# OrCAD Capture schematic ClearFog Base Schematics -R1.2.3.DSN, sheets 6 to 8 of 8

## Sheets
6 MicroUSB_UART + Fan + SFP: size C; title: MikroUSB_UART + Fan + SFP
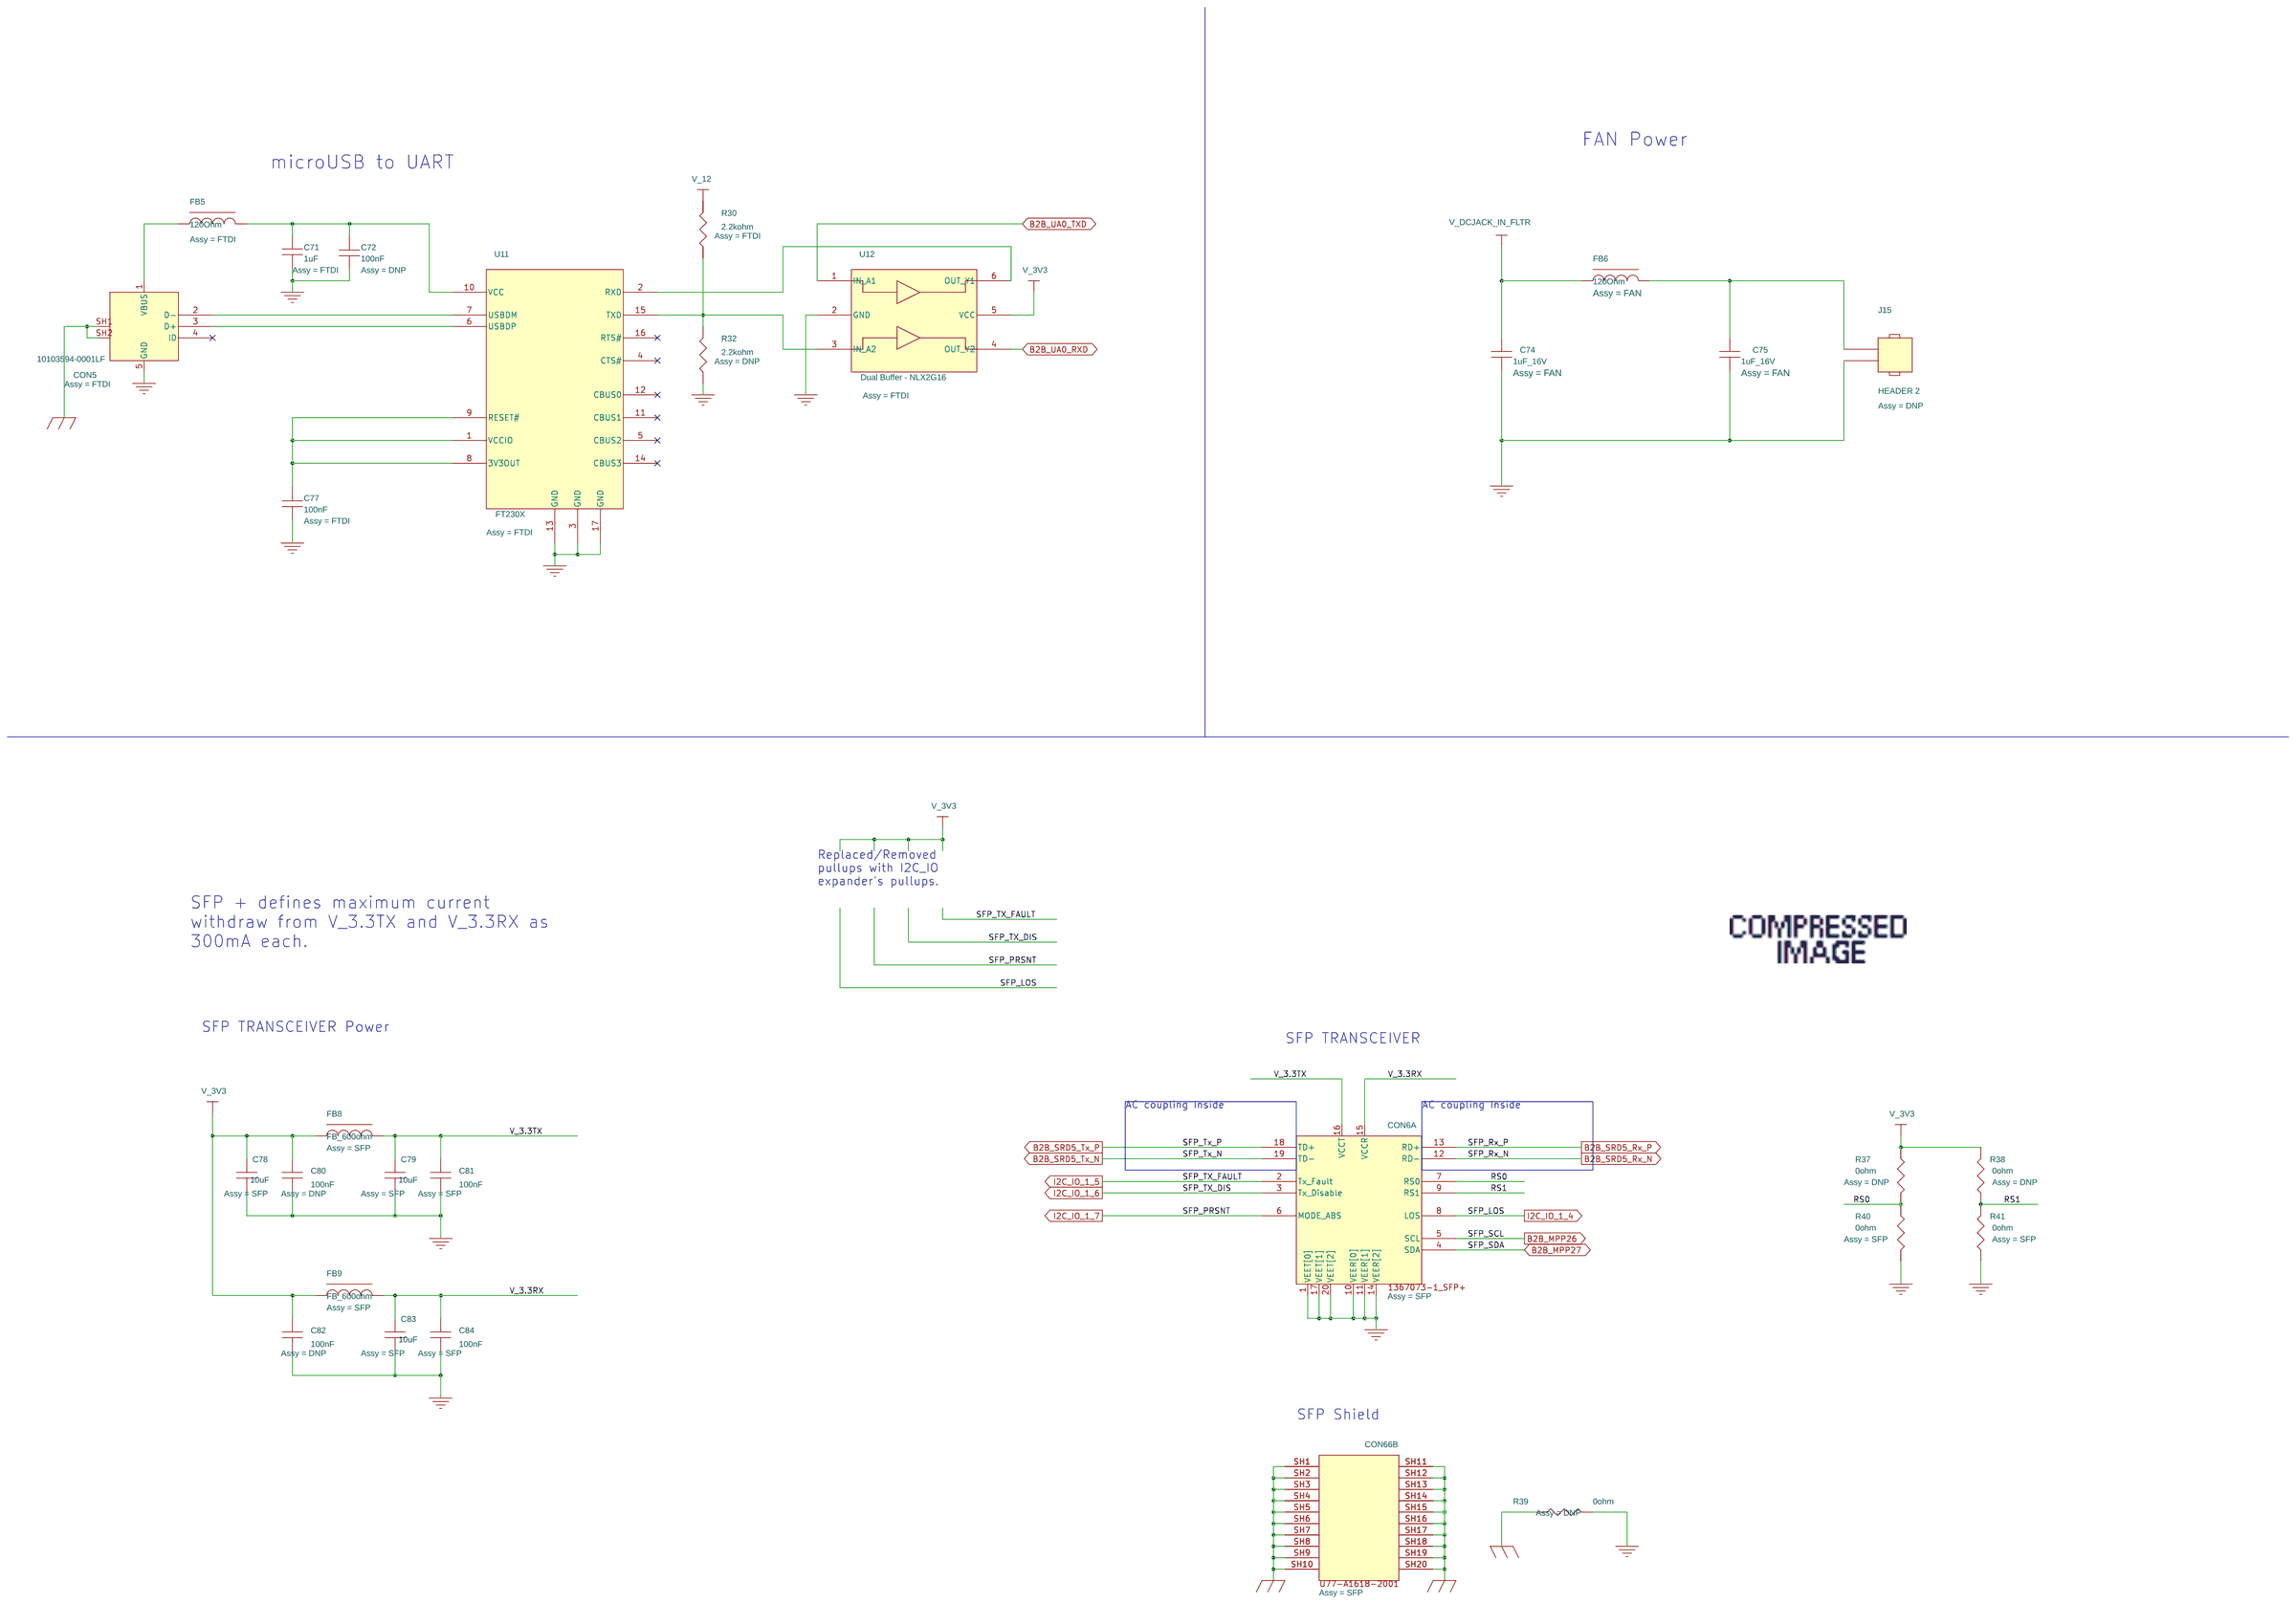
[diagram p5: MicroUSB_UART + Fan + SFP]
7 GE PHY1 + RJ45: size C; title: GE PHY1 + RJ45
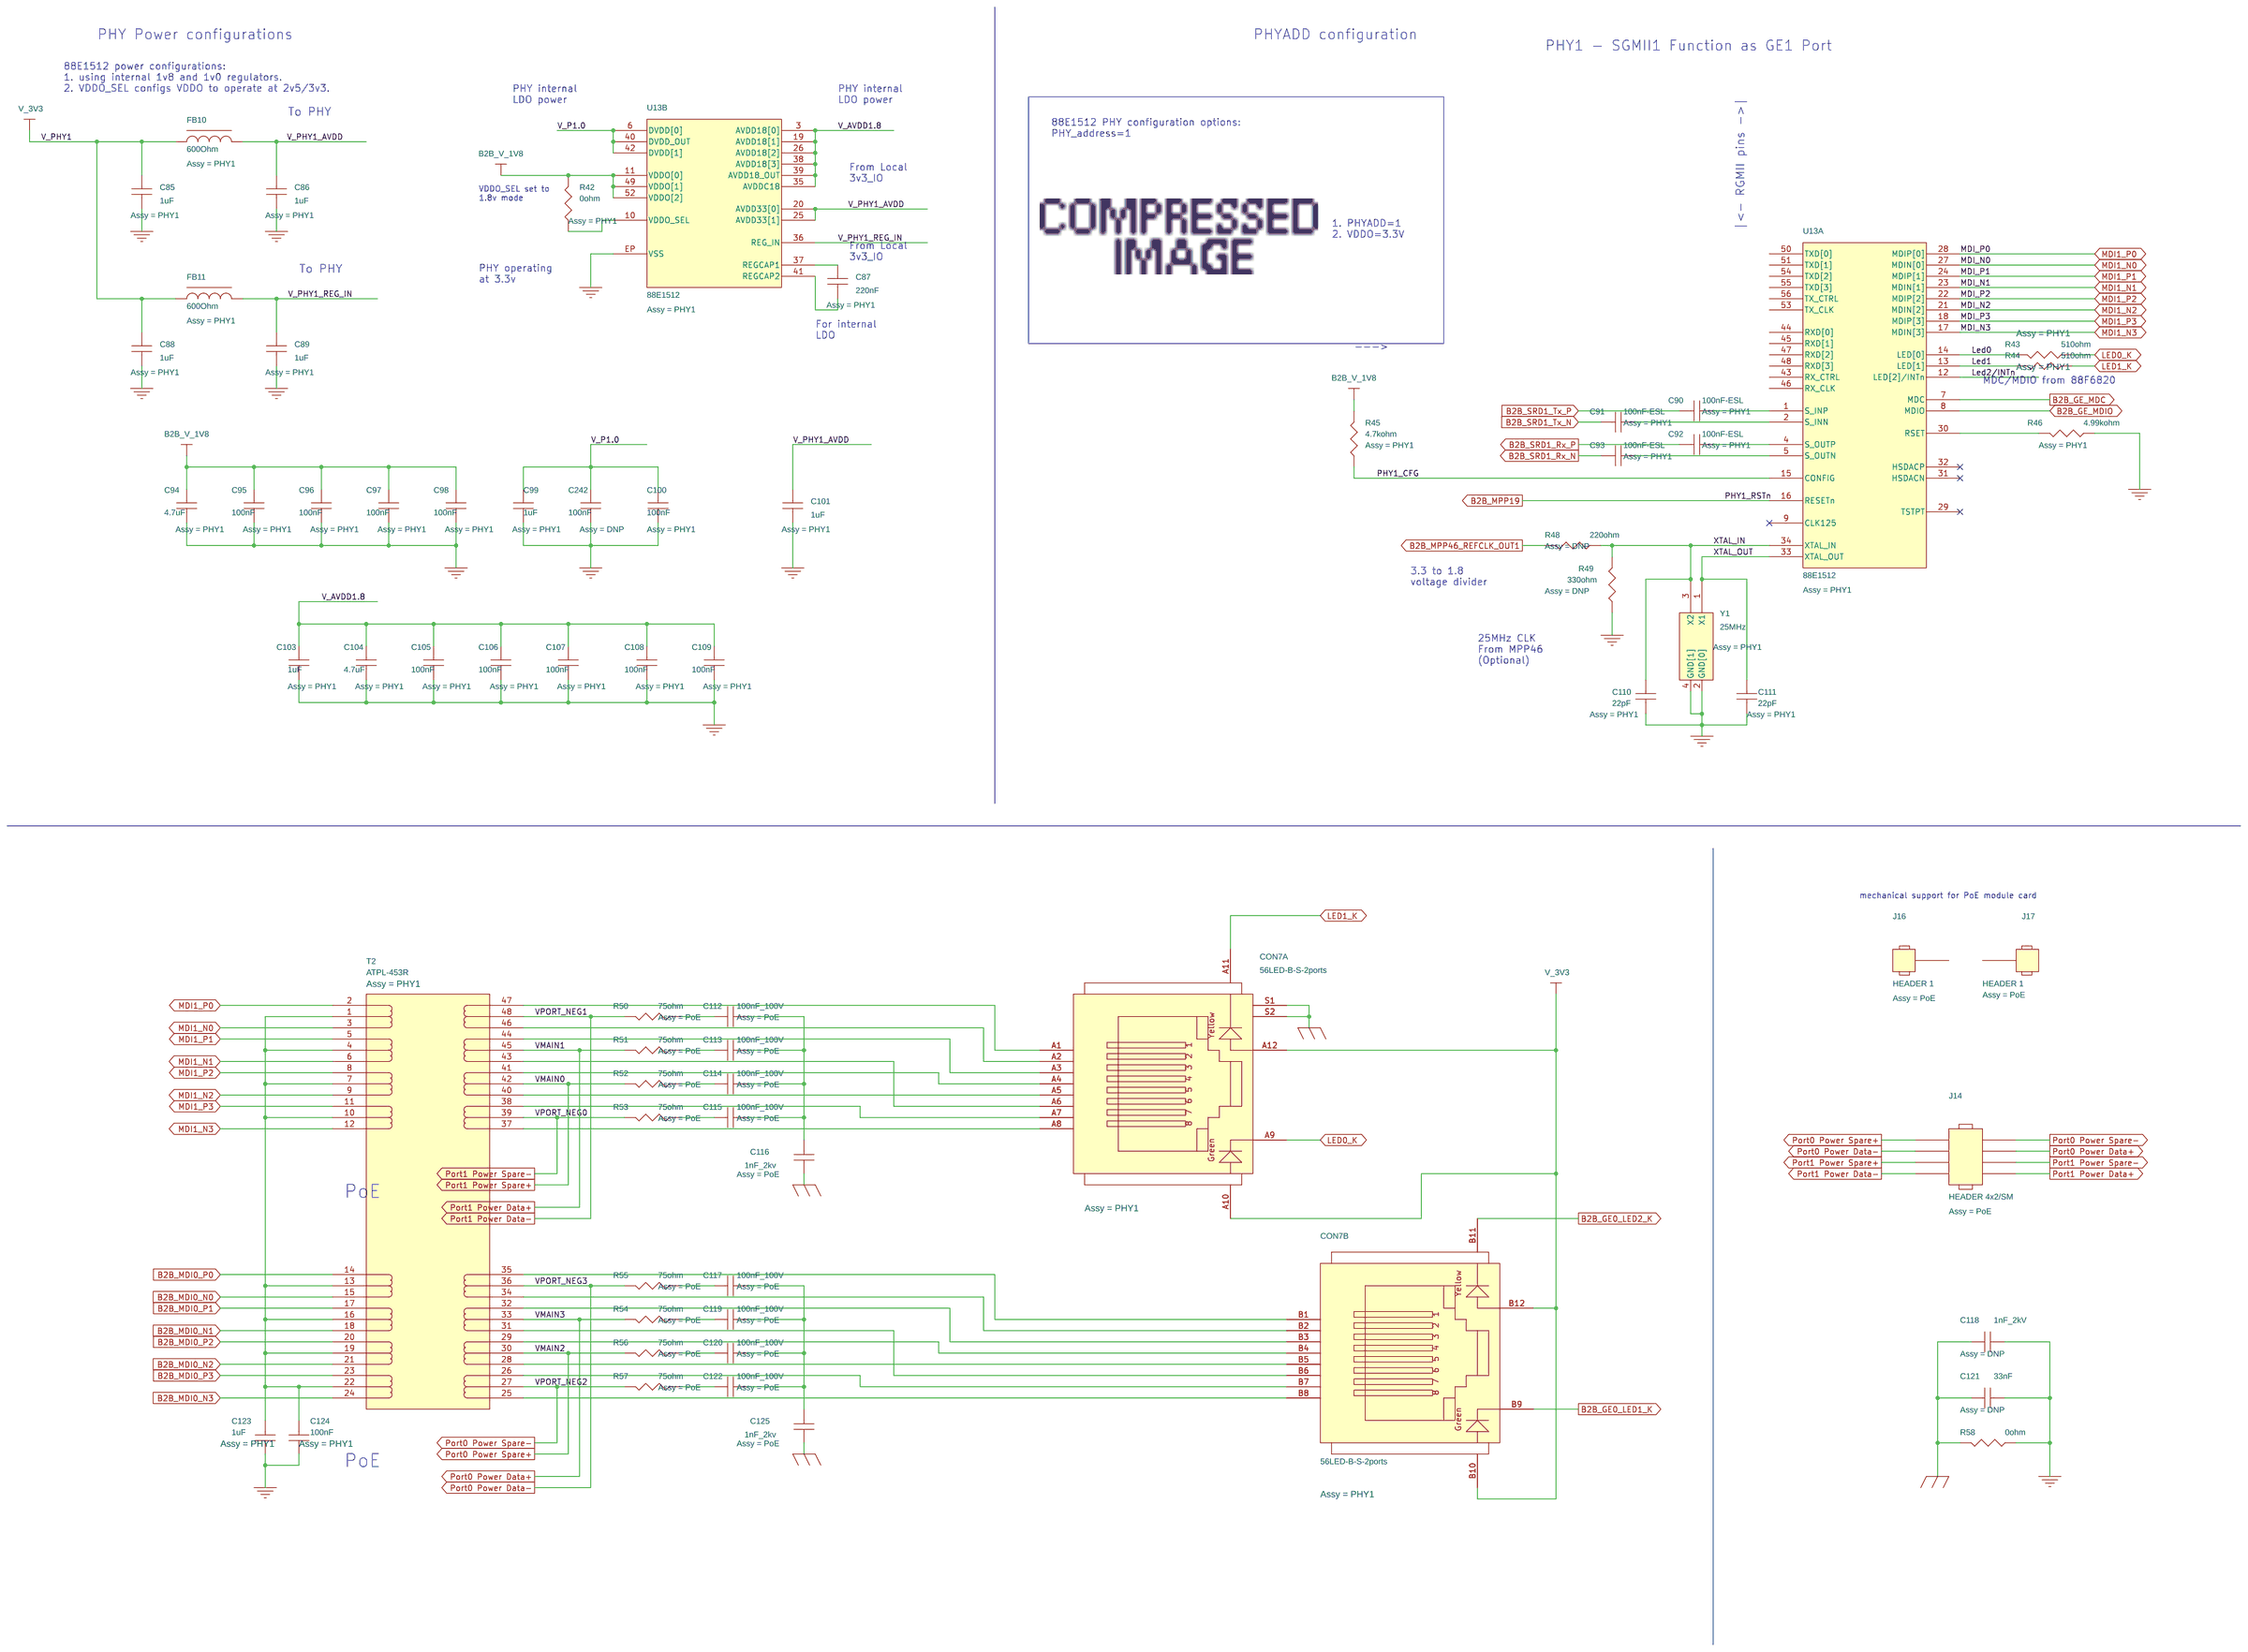
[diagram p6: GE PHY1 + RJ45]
8 Mikrobus + Booting + IO_Ex: size C; title: Mikrobus + Booting + IO_Ex
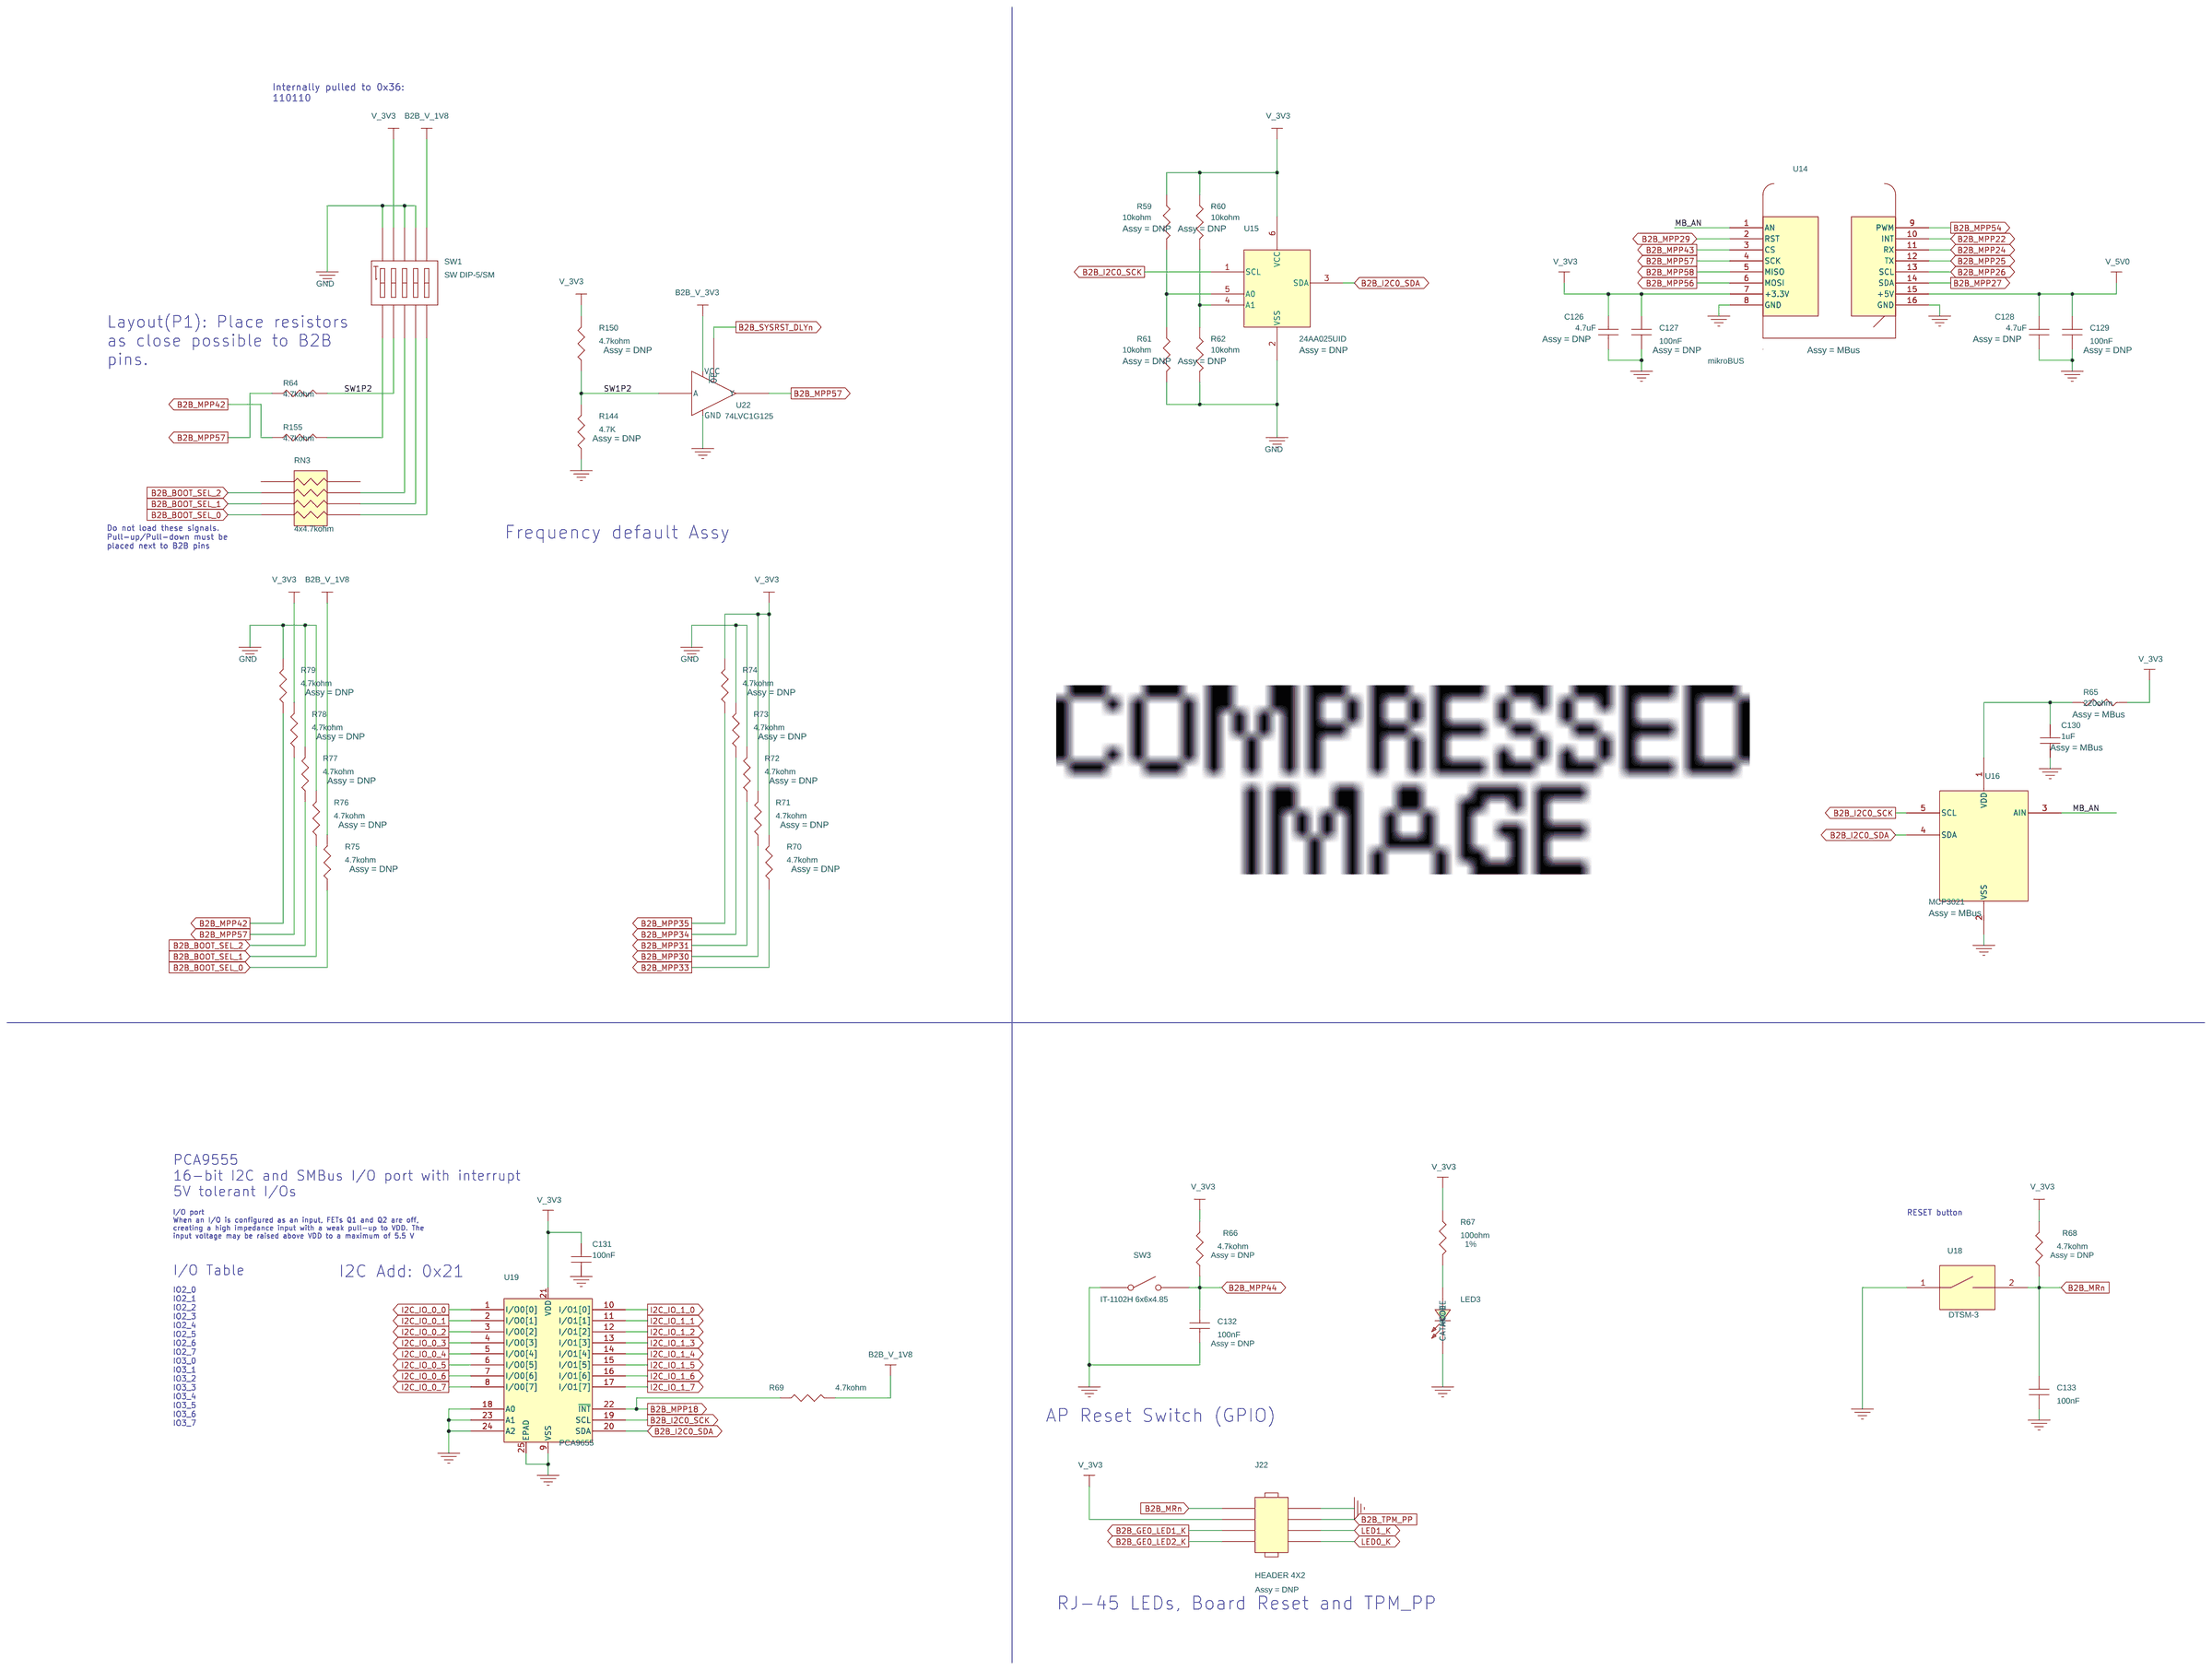
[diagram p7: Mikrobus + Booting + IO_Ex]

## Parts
sheet GE PHY1 + RJ45
C85  1uF  [C0402]
C86  1uF  [C0402]
C87  220nF  [C0402]
C88  1uF  [C0402]
C89  1uF  [C0402]
C90  100nF-ESL  [C0402]
C91  100nF-ESL  [C0402]
C92  100nF-ESL  [C0402]
C93  100nF-ESL  [C0402]
C94  4.7uF  [C0603]
C95  100nF  [C0402]
C96  100nF  [C0402]
C97  100nF  [C0402]
C98  100nF  [C0402]
C99  1uF  [C0402]
C100  100nF  [C0402]
C101  1uF  [C0402]
C103  1uF  [C0402]
C104  4.7uF  [C0603]
C105  100nF  [C0402]
C106  100nF  [C0402]
C107  100nF  [C0402]
C108  100nF  [C0402]
C109  100nF  [C0402]
C110  22pF  [C0402]
C111  22pF  [C0402]
C112  100nF_100V  [C0603]
C113  100nF_100V  [C0603]
C114  100nF_100V  [C0603]
C115  100nF_100V  [C0603]
C116  1nF_2kv  [C1210]
C117  100nF_100V  [C0603]
C118  1nF_2kV  [C1210]
C119  100nF_100V  [C0603]
C120  100nF_100V  [C0603]
C121  33nF  [C0402]
C122  100nF_100V  [C0603]
C123  1uF  [C0402]
C124  100nF  [C0402]
C125  1nF_2kv  [C1210]
C242  100nF  [C0402]
CON7  56LED-B-S-2ports  [RJ45x2]  (sections A,B)
FB10  600Ohm  [L0603]
FB11  600Ohm  [L0603]
J14  HEADER 4x2/SM
J16  HEADER 1
J17  HEADER 1
R42  0ohm  [R0402]
R43  510ohm  [R0402]
R44  510ohm  [R0402]
R45  4.7kohm  [R0402]
R46  4.99kohm  [R0402]
R48  220ohm  [R0402]
R49  330ohm  [R0402]
R50  75ohm  [R0402]
R51  75ohm  [R0402]
R52  75ohm  [R0402]
R53  75ohm  [R0402]
R54  75ohm  [R0402]
R55  75ohm  [R0402]
R56  75ohm  [R0402]
R57  75ohm  [R0402]
R58  0ohm  [R0402]
T2  ATPL-453R  [ATPL-453R]
U13  88E1512  [QFN56_8X8_0P50_EP_4p57]  (sections A,B)
Y1  25MHz  [S3225]
sheet MicroUSB_UART + Fan + SFP
C71  1uF  [C0402]
C72  100nF  [C0402]
C74  1uF_16V  [C0603]
C75  1uF_16V  [C0603]
C77  100nF  [C0402]
C78  10uF  [C0603]
C79  10uF  [C0603]
C80  100nF  [C0402]
C81  100nF  [C0402]
C82  100nF  [C0402]
C83  10uF  [C0603]
C84  100nF  [C0402]
CON5  10103594-0001LF  [NA]
CON6  1367073-1__U77-A1618-2001  [1367073-1__U77-A1618-2001]  (section A)
CON66  1367073-1__U77-A1618-2001  [1367073-1__U77-A1618-2001]  (section B)
FB5  120Ohm  [L0603]
FB6  120Ohm  [L0603]
FB8  FB_600ohm  [L0402]
FB9  FB_600ohm  [L0402]
J15  HEADER 2  [2x100mil]
R30  2.2kohm  [402]
R32  2.2kohm  [402]
R37  0ohm  [R0402]
R38  0ohm  [R0402]
R39  0ohm  [R0402]
R40  0ohm  [R0402]
R41  0ohm  [R0402]
U11  FT230X  [QFN16]
U12  Dual Buffer - NLX2G16  [ULLGA6-CASE613AE]
sheet Mikrobus + Booting + IO_Ex
C126  4.7uF  [C0603]
C127  100nF  [C0402]
C128  4.7uF  [C0603]
C129  100nF  [C0402]
C130  1uF  [C0402]
C131  100nF  [C0402]
C132  100nF  [C0402]
C133  100nF  [C0402]
J22  HEADER 4X2
LED3  LED  [N/A]
R59  10kohm  [R0402]
R60  10kohm  [R0402]
R61  10kohm  [R0402]
R62  10kohm  [R0402]
R64  4.7kohm  [R0402]
R65  220ohm  [R0402]
R66  4.7kohm  [R0402]
R67  100ohm  [R0402]
R68  4.7kohm  [R0402]
R69  4.7kohm  [R0402]
R70  4.7kohm  [R0402]
R71  4.7kohm  [R0402]
R72  4.7kohm  [R0402]
R73  4.7kohm  [R0402]
R74  4.7kohm  [R0402]
R75  4.7kohm  [R0402]
R76  4.7kohm  [R0402]
R77  4.7kohm  [R0402]
R78  4.7kohm  [R0402]
R79  4.7kohm  [R0402]
R144  4.7K  [R0402]
R150  4.7kohm  [R0402]
R155  4.7kohm  [R0402]
RN3  4x4.7kohm  [4xR0402]
SW1  SW DIP-5/SM
SW3  IT-1102H 6x6x4.85
U14  mikroBUS  [mikroBUS]
U15  24AA025UID  [SOT-23]
U16  MCP3021  [SOT-23A]
U18  DTSM-3  [DTSM-3]
U19  PCA9655  [WQFN24]
U22  74LVC1G125  [SOT-353-1]

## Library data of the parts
C85 C86 C88 C89 C99 C101 C103 = Cap: CAP CER 0402 1uF 10V 10% X5R; Assy: PHY1; Manufacturer: samsung; Manufacturer Name: samsung; Manufacturer P/N: CL05A105KP5NNNC; Part Number: C1050603-X7R-16V; SolidRun P/N: CA20005; Updated: 2016-02-10 17:13:33; Datasheet: <null>
C87 = Cap: CAP CER 0402 0.22uF 6.3V 10% X5R; Assy: PHY1; Manufacturer: Murata; Manufacturer Name: Murata; Manufacturer P/N: GRM155R60J224KE01D; Part Number: C2240603-X7R-50V; SolidRun P/N: CA20016; Updated: 2016-02-10 17:13:33; Datasheet: <null>
C90-C93 = Cap: CAP CER 100NF 16V 10% X7R 0402; Assy: PHY1; FPLIST: 0402_SQR21,0402_RND,0402; Manufacturer: CAPAX; Manufacturer Name: CAPAX; Manufacturer P/N: 0402X104K250SNT; Part Number: 0402X104K250SNT; SolidRun P/N: CA20090; Updated: 2016-02-10 17:13:33; Datasheet: <null>
C94 C104 = Cap: CAP CER 0603 4.7UF 10V 10% X5R; Assy: PHY1; Manufacturer: Hitano; Manufacturer Name: Hitano; Manufacturer P/N: 0603B475K160NU; Part Number: C4750805-X5R-25V; SolidRun P/N: CA30003; Updated: 2016-02-10 17:13:33; Datasheet: <null>
C95-C98 C100 C105-C109 = Cap: CAP CER 0402 100nF 10V 10% X7R; Assy: PHY1; Manufacturer: samsung; Manufacturer Name: samsung; Manufacturer P/N: CL05B104KP5NNNC; Part Number: C1040402-X7R-16V; SolidRun P/N: CA20001; Updated: 2016-02-10 17:13:33; Datasheet: <null>
C110 C111 = Cap: CAP CER 0402 22pF 50V 5% C0G; Assy: PHY1; Manufacturer: Murata; Manufacturer Name: Murata; Manufacturer P/N: GRM1555C1H220JA01D; Part Number: C2200402-NPO-50V; SolidRun P/N: CA20080; Updated: 2016-02-10 17:13:33; Datasheet: <null>
C112-C115 C117 C119 C120 C122 = Cap: CAP CER 0.1 uF 100 V 10% X7R 0603; Assy: PoE; FPLIST: 0402_SQR21,0402_RND,0402; Manufacturer: samsung; Manufacturer Name: samsung; Manufacturer P/N: CL10B104KC8NNNC; Part Number: C1040402-X7R-16V; SolidRun P/N: CA30006; Updated: 2016-02-10 17:13:33; Datasheet: <null>
C116 C125 = Cap: CHIP CAP 1nF 2KV 1610; Assy: PoE; MFG_NAME01: Hitano; MFG_PN01: 1210N102J202NT; Manufacturer: Hitano; Manufacturer Name: Hitano; Manufacturer P/N: 1210N102J202NT; PRIORITY_PN: CA60001; SolidRun P/N: CA60001; Updated: 2016-02-10 17:13:33; Datasheet: <null>
C118 = Cap: CHIP CAP 1nF 2KV 1610; Assy: DNP; MFG_NAME01: Hitano; MFG_PN01: 1210N102J202NT; Manufacturer: Hitano; Manufacturer P/N: 1210N102J202NT; PRIORITY_PN: CA60001; SolidRun P/N: CA60001; Updated: 2015-02-17 20:35:06; Datasheet: <null>
C121 = Cap: CHIP CAP 33nF 6.3V 0402 X5R; Assy: DNP; MFG_NAME01: SAMSUNG; MFG_PN01: CL05B333KP5NNNC; Manufacturer: Murata; Manufacturer Name: Murata; Manufacturer P/N: GRM155R71A333KA01D; SolidRun P/N: CA20011; Updated: 2016-02-10 17:13:33; Datasheet: <null>
C123 = Cap: CAP CER 0402 1uF 10V 10% X5R; Assy: PHY1; MFG_NAME01: SAMSUNG; MFG_PN01: CL05B333KP5NNNC; Manufacturer: samsung; Manufacturer Name: samsung; Manufacturer P/N: CL05A105KP5NNNC; PRIORITY_PN: CA20005; SolidRun P/N: CA20005; Updated: 2016-02-10 17:13:33; Datasheet: <null>
C124 = Cap: CAP CER 0402 100nF 10V 10% X7R; Assy: PHY1; FPLIST: 0402_SQR21,0402_RND,0402; Manufacturer: samsung; Manufacturer Name: samsung; Manufacturer P/N: CL05B104KP5NNNC; Part Number: C1040402-X7R-16V; SolidRun P/N: CA20001; Updated: 2016-02-10 17:13:33; Datasheet: <null>
C242 = Cap: CAP CER 0402 100nF 10V 10% X7R; Assy: DNP; Manufacturer: samsung; Manufacturer Name: samsung; Manufacturer P/N: CL05B104KP5NNNC; Part Number: C1040402-X7R-16V; SolidRun P/N: CA20001; Updated: 2016-02-10 17:13:33; Datasheet: <null>
CON7 = 56LED-B-S-2ports_1: RJ45 2x1, With LEDs, WO magnetics; Assy: PHY1; Manufacturer Name: Data JDE; Manufacturer P/N: B563S2-8806-M002; SolidRun P/N: CO00543; Tolerance: <null>; Updated: 2016-02-10 17:13:33
FB10 FB11 = Ferrite_Bead: Multilayer Ferrite Chip Beads 600 OHM; Assy: PHY1; Manufacturer: chilisin; Manufacturer Name: chilisin; Manufacturer P/N: PBY160808T-601Y-N; Part Number: PBY160808T-601Y-N; SolidRun P/N: IN00012; Updated: 2016-02-10 17:13:33; Datasheet: http://www.chilisin.com.tw/proimages/product_line_up_pdf/Chip%20Beads%20PB%20Series.pdf
J14 = HEADER_4x2_SM: 2x4 100 mil simple header; Assy: PoE; Manufacturer Name: <null>; Manufacturer P/N: <null>; SolidRun P/N: CO00568; Tolerance: <null>; Updated: 2016-02-10 17:13:33; Datasheet: <null>
J16 J17 = HEADER_1: 100 mil header 1 x 1; Assy: PoE; Manufacturer Name: cvilux; Manufacturer P/N: CH31012V200-NH; SolidRun P/N: CO00517
R42 = Resistor: RES 0402 1/16W 0? 5%; Assy: PHY1; Manufacturer: Yageo; Manufacturer Name: Yageo; Manufacturer P/N: RC0402JR-070RL; Manufacturer's Part Number: RC0402JR-070RL; Part Number: R0000402; SolidRun P/N: RE20009; Updated: 2016-02-10 17:13:33; Datasheet: <null>
R43 R44 = Resistor: RES 0402 1/16W 510? 5%; Assy: PHY1; Manufacturer: Yageo; Manufacturer Name: Yageo; Manufacturer P/N: RC0402JR-07510RL; Part Number: R5110402-1%; Power: <null>; SolidRun P/N: RE20022; Tolerance: 5%; Updated: 2016-02-10 17:13:33; Datasheet: <null>
R45 = Resistor: RES 0402 1/16W 4.7K? 1%; Assy: PHY1; Manufacturer: Yageo; Manufacturer Name: Yageo; Manufacturer P/N: RC0402FR-074K7L; Part Number: R4720402-1%; SolidRun P/N: RE20002; Updated: 2016-02-10 17:13:33; Datasheet: <null>
R46 = Resistor: RES 0402 1/16W 4.99K? 1%; Assy: PHY1; Manufacturer: Yageo; Manufacturer Name: Yageo; Manufacturer P/N: RC0402FR-074K99L; Part Number: R49A920402-1%; SolidRun P/N: RE20026; Updated: 2016-02-10 17:13:33; Datasheet: <null>
R48 = Resistor: RES 0402 1/16W 220? 1%; Assy: DNP; Manufacturer: Yageo; Manufacturer Name: Yageo; Manufacturer P/N: RC0402FR-07220RL; Part Number: R2210402-1%; SolidRun P/N: RE20103; Updated: 2016-02-10 17:13:33; Datasheet: <null>
R49 = Resistor: RES 0402 1/16W 330? 1%; Assy: DNP; Manufacturer: Yageo; Manufacturer Name: Yageo; Manufacturer P/N: RC0402FR-07330RL; Part Number: R3310402-1%; SolidRun P/N: RE20209; Updated: 2016-02-10 17:13:33; Datasheet: <null>
R50-R57 = Resistor_tolerance_0: RES 0402 1/16W 75 1%; Assy: PoE; FPLIST: RC0402_25,RC0402_HD,RC0402_X2,0402_CC; MFG_NAME01: YAGEO; MFG_PN01: RC0402JR-070RL; Manufacturer: Yageo; Manufacturer Name: Yageo; Manufacturer P/N: RC0402FR-0775RL; SolidRun P/N: RE20401; Updated: 2016-02-10 17:13:33; Datasheet: <null>
R58 = Resistor_tolerance_0: RES 0402 1/16W 0? 5%; FPLIST: RC0402_25,RC0402_HD,RC0402_X2,0402_CC; MFG_NAME01: YAGEO; MFG_PN01: RC0402JR-070RL; Manufacturer: Yageo; Manufacturer Name: Yageo; Manufacturer P/N: RC0402JR-070RL; SolidRun P/N: RE20009; Updated: 2016-02-10 17:13:33; Datasheet: <null>
T2 = ATPL-456R_0: 1000 BASE ?T DUAL PORT PoE PLUS MAGNETICS MODULE SMT; Assy: PHY1; Manufacturer Name: <null>; Manufacturer P/N: <null>; SolidRun P/N: IC01002; Tolerance: <null>; Updated: 2016-02-10 17:13:33; Datasheet: <null>
U13 = 88E1512-AX: Marvell ALASKA 10/100/1000 Ethernet PHY; Assy: PHY1; Manufacturer: Marvell; Manufacturer Name: Marvell; Manufacturer P/N: 88E1512-A0-NNP2C000; Part Number: 88E1512-A0-NNP2C000; SolidRun P/N: IC00304; Updated: 2016-02-10 17:13:33
Y1 = CXA-025000: 25MHz 3.2mm x 2.5mm xyz ppm; Assy: PHY1; Manufacturer: YOKETAN; Manufacturer Name: YOKETAN; Manufacturer P/N: S3225A025000-F10CCCA; Part Number: CXA-025000-3X4X23; SolidRun P/N: OC00002; Updated: 2016-02-10 17:13:33; Datasheet: <null>
C71 = Cap: CAP CER 0402 1uF 10V 10% X5R; Assy: FTDI; MFG_NAME01: SAMSUNG; MFG_PN01: CL05A105KP5NNNC; Manufacturer: samsung; Manufacturer Name: samsung; Manufacturer P/N: CL05A105KP5NNNC; PRIORITY_PN: CA20005; SolidRun P/N: CA20005; Updated: 2016-02-10 17:13:33; VOLTAGE: 10V; WVDC: 10V; Datasheet: <null>
C72 = Cap: CAP CER 0402 100nF 10V 10% X7R; Assy: DNP; Manufacturer: samsung; Manufacturer Name: samsung; Manufacturer P/N: CL05B104KP5NNNC; Note: Using 16V instead of 6.3V; Part Number: 0402X104K250SNT; Price: 0.003; SolidRun P/N: CA20001; Source: Mouser; Source P/N: 81-GRM155R71C104KA88; Updated: 2016-02-10 17:13:33; Datasheet: <null>
C74 C75 = Cap: 1uF 16V 0603; Assy: FAN; Part Number: C1050603-X7R-16V; SolidRun P/N: CA30013; Tolerance: 10%; Updated: 2016-02-10 17:13:33
C77 = Cap: CAP CER 0402 100nF 10V 10% X7R; Assy: FTDI; Manufacturer: samsung; Manufacturer Name: samsung; Manufacturer P/N: CL05B104KP5NNNC; Note: Using 16V instead of 6.3V; Part Number: 0402X104K250SNT; Price: 0.003; SolidRun P/N: CA20001; Source P/N: 81-GRM155R71C104KA88; Updated: 2016-02-10 17:13:33; Datasheet: <null>
C78 C79 C83 = Cap: CAP CER 0603 10UF 6.3V 10% X5R; Assy: SFP; Manufacturer: Samsung; Manufacturer Name: Samsung; Manufacturer P/N: CL10A106KQ8NNNC; Part Number: C1060805-X5R-16V; SolidRun P/N: CA30001; Updated: 2016-02-10 17:13:33; Datasheet: <null>
C80 C82 C127 C129 C132 = Cap: CAP CER 0402 100nF 10V 10% X7R; Assy: DNP; FPLIST: 0402_SQR21,0402_RND,0402; Manufacturer: samsung; Manufacturer Name: samsung; Manufacturer P/N: CL05B104KP5NNNC; Part Number: C1040402-X7R-16V; SolidRun P/N: CA20001; Updated: 2016-02-10 17:13:33; Datasheet: <null>
C81 C84 = Cap: CAP CER 0402 100nF 10V 10% X7R; Assy: SFP; FPLIST: 0402_SQR21,0402_RND,0402; Manufacturer: samsung; Manufacturer Name: samsung; Manufacturer P/N: CL05B104KP5NNNC; Part Number: C1040402-X7R-16V; SolidRun P/N: CA20001; Updated: 2016-02-10 17:13:33; Datasheet: <null>
CON5 = CU04SCH15B0_1: microUSB Type B connector; Assy: FTDI; Manufacturer: FCI; Manufacturer Name: FCI; Note: USB micro type B; PRIORITY_PN: CO00005; Part Number: CU04SCH15B0; Price: 0.3; SolidRun P/N: CO00005; Source P/N: 649-10103594-0001LF; Updated: 2016-02-10 17:13:33; Datasheet: http://portal.fciconnect.com/Comergent//fci/drawing/10103594.pdf
CON6 = 1367073-1_SFP+_U77-A1618-2x0x: SF Plus (SFP) Connector and housing; Assy: SFP; Manufacturer: CZT; Manufacturer Name: Ampheonol; Manufacturer P/N: U77-A1618-2001; SolidRun P/N: CO00042; Updated: 2016-02-10 17:13:33; Datasheet: http://media.digikey.com/PDF/Data%20Sheets/Amphenol%20PDFs/P-U77-A1618-2x0x.pdf
CON66 = 1367073-1_SFP+_U77-A1618-2x0x: SF Plus (SFP) Connector and housing; Assy: SFP; Manufacturer: Ampheonol; Manufacturer Name: Ampheonol; Manufacturer P/N: U77-A1618-2001; SolidRun P/N: CO00054; Updated: 2016-02-10 17:13:33; Datasheet: http://media.digikey.com/PDF/Data%20Sheets/Amphenol%20PDFs/P-U77-A1618-2x0x.pdf
FB5 = Ferrite_Bead: Bead 120ohm, 100MHz, 2A; Assy: FTDI; Manufacturer: muRata; Manufacturer Name: muRata; Manufacturer P/N: BLM18PG121SN1D; Note: Bead Ferrite; Part Number: BLM18PG121SN1D; Price: 0.025; SolidRun P/N: IN00003; Source: Mouser; Source P/N: 81-BLM18PG121SN1D; Updated: 2016-02-10 17:13:33; Datasheet: http://search.murata.co.jp/Ceramy/image/img/PDF/ENG/L0110S0100BLM18P.pdf
FB6 = Ferrite_Bead: Bead 120ohm, 100MHz, 2A; Assy: FAN; Manufacturer: muRata; Manufacturer Name: muRata; Manufacturer P/N: BLM18PG121SN1D; Note: Bead Ferrite; Part Number: BLM18PG121SN1D; SolidRun P/N: IN00003; Updated: 2016-02-10 17:13:33; Datasheet: http://search.murata.co.jp/Ceramy/image/img/PDF/ENG/L0110S0100BLM18P.pdf
FB8 FB9 = Ferrite_Bead: Multilayer Ferrite Chip Beads 0402 600ohm 500mA +/-25%; Assy: SFP; Manufacturer: Murata; Manufacturer Name: Murata; Manufacturer P/N: BLM15AX601SN1D; Part Number: BLM15AX601SN1D; Power: <null>; SolidRun P/N: IN00013; Tolerance: 1.0A 25%; Updated: 2016-02-10 17:13:33; Datasheet: <null>
J15 = HEADER_2: Two pin through hole header. 100 mil spacing; Assy: DNP; Manufacturer Name: <null>; Manufacturer P/N: <null>; SolidRun P/N: CO00049; Tolerance: <null>; Updated: 2016-02-10 17:13:33; Datasheet: <null>
R30 = Resistor: CHIP RES 2.2K 1/16W 0402; Assy: FTDI; Manufacturer: YAGEO; Manufacturer Name: YAGEO; Manufacturer P/N: RC0402JR-072K2L; PRIORITY_PN: RE20204; SolidRun P/N: RE20204; Tolerance: 5%; Updated: 2016-02-10 17:13:33; Datasheet: <null>
R32 = Resistor: CHIP RES 2.2K 1/16W 0402; Assy: DNP; Manufacturer: YAGEO; Manufacturer Name: YAGEO; Manufacturer P/N: RC0402JR-072K2L; PRIORITY_PN: RE20204; SolidRun P/N: RE20204; Tolerance: 5%; Updated: 2016-02-10 17:13:33; Datasheet: <null>
R37 R38 = Resistor: RES 0402 1/16W 0? 5%; Assy: DNP; FPLIST: 0402_SQR21,0402_RND,0402; Manufacturer: Yageo; Manufacturer Name: Yageo; Manufacturer P/N: RC0402JR-070RL; Part Number: R0000402; SolidRun P/N: RE20009; Updated: 2016-02-10 17:13:33; Datasheet: <null>
R39 = Resistor: RES 0402 1/16W 0? 5%; Assy: DNP; Manufacturer: Yageo; Manufacturer Name: Yageo; Manufacturer P/N: RC0402JR-070RL; Part Number: R0000805; SolidRun P/N: RE20009; Updated: 2016-02-10 17:13:33; Datasheet: <null>
R40 R41 = Resistor: RES 0402 1/16W 0? 5%; Assy: SFP; FPLIST: 0402_SQR21,0402_RND,0402; Manufacturer: Yageo; Manufacturer Name: Yageo; Manufacturer P/N: RC0402JR-070RL; Part Number: R0000402; SolidRun P/N: RE20009; Updated: 2016-02-10 17:13:33; Datasheet: <null>
U11 = FT230X_4: UART interfaceÿsupportÿfor 7 or 8 data bits; Assy: FTDI; Manufacturer: FTDI; Manufacturer Name: FTDI; Manufacturer P/N: FT230XQ-R; Part Number: FT230XQ-R; SolidRun P/N: IC00015; Source: TriTech; Source P/N: FT230XQ-R; Updated: 2016-02-10 17:13:33; Datasheet: http://www.ftdichip.com/Support/Documents/DataSheets/ICs/DS_FT230X.pdf
U12 = Dual_Buffer: Assy: FTDI; Manufacturer: ON SEMI; Manufacturer Name: ON SEMI; Manufacturer P/N: NLX2G16AMX1TCG; SolidRun P/N: IC00300; Updated: 2016-02-10 17:13:33; Datasheet: http://www.onsemi.com/pub_link/Collateral/NLX2G16-D.PDF
C126 C128 = Cap: CAP CER 0603 4.7UF 10V 10% X5R; Assy: DNP; Manufacturer: Hitano; Manufacturer Name: Hitano; Manufacturer P/N: 0603B475K160NU; Part Number: C4750805-X5R-25V; SolidRun P/N: CA30003; Updated: 2016-02-10 17:13:33; Datasheet: <null>
C130 = Cap: CAP CER 0402 1uF 10V 10% X5R; Assy: MBus; Manufacturer: samsung; Manufacturer Name: samsung; Manufacturer P/N: CL05A105KP5NNNC; Part Number: C1050603-X7R-16V; SolidRun P/N: CA20005; Updated: 2016-02-10 17:13:33; Datasheet: <null>
C131 = Cap: CAP CER 0402 100nF 10V 10% X7R; FPLIST: 0402_SQR21,0402_RND,0402; Manufacturer: samsung; Manufacturer Name: samsung; Manufacturer P/N: CL05B104KP5NNNC; Package: 0603; Part Number: C1040402-X7R-16V; SolidRun P/N: CA20001; Updated: 2016-02-10 17:13:33; Datasheet: <null>
C133 = Cap: CAP CER 0402 100nF 10V 10% X7R; FPLIST: 0402_SQR21,0402_RND,0402; Manufacturer: samsung; Manufacturer Name: samsung; Manufacturer P/N: CL05B104KP5NNNC; Part Number: C1040402-X7R-16V; SolidRun P/N: CA20001; Updated: 2016-02-10 17:13:33; Datasheet: <null>
J22 = HEADER_4X2: 50 mil header 2 x 4; Assy: DNP; Manufacturer: Cvilux; Manufacturer Name: Cvilux; Manufacturer P/N: CH52082V100; SolidRun P/N: CO00579; Datasheet: http://www.cvilux.com.tw/upload/catalog/H-CH.pdf
LED3 = LED: Indication LED 0603 - Green; Manufacturer: Everlight; Manufacturer Name: Everlight; PRIORITY_PN: DI00210; SolidRun P/N: DI00210; Updated: 2016-02-10 17:13:33; Datasheet: http://download.siliconexpert.com/pdfs/2007/08/07/semi_b/manual/ele/lamps/ds300089.pdf
R59-R62 = Resistor: RES 0402 1/16W 10K? 1%; Assy: DNP; Manufacturer: Yageo; Manufacturer Name: Yageo; Manufacturer P/N: RC0402FR-0710KL; Part Number: R1030402-1%; SolidRun P/N: RE20013; Updated: 2016-02-10 17:13:33; Datasheet: <null>
R64 R69 R155 = Resistor: RES 0402 1/16W 4.7K? 1%; Manufacturer: Yageo; Manufacturer Name: Yageo; Manufacturer P/N: RC0402FR-074K7L; Part Number: R1030402-1%; SolidRun P/N: RE20002; Updated: 2016-02-10 17:13:33; Datasheet: <null>
R65 = Resistor: RES 0402 1/16W 220? 1%; Assy: MBus; Manufacturer: Yageo; Manufacturer Name: Yageo; Manufacturer P/N: RC0402FR-07220RL; Part Number: R2210402-1%; SolidRun P/N: RE20103; Updated: 2016-02-10 17:13:33; Datasheet: <null>
R66 R68 = Resistor: RES 0402 1/16W 4.7K? 1%; Assy: DNP; FPLIST: 0402_SQR21,0402_RND,0402; Manufacturer: Yageo; Manufacturer Name: Yageo; Manufacturer P/N: RC0402FR-074K7L; Part Number: R4720402-1%; SolidRun P/N: RE20002; Updated: 2016-02-10 17:13:33; Datasheet: <null>
R67 = Resistor: RES 0402 1/16W 100 1%; Manufacturer: Yageo; Manufacturer Name: Yageo; Manufacturer P/N: RC0402FR-07100RL; Part Number: R1010402-1%; Power: <null>; SolidRun P/N: RE20207; Tolerance: 1%; Updated: 2016-02-10 17:13:33; Datasheet: <null>
R70-R79 R150 = Resistor: RES 0402 1/16W 4.7K? 1%; Assy: DNP; Manufacturer: Yageo; Manufacturer Name: Yageo; Manufacturer P/N: RC0402FR-074K7L; Part Number: R1030402-1%; SolidRun P/N: RE20002; Updated: 2016-02-10 17:13:33; Datasheet: <null>
R144 = Resistor: RES 0402 1/16W 4.7K? 1%; Assy: DNP; Manufacturer: Yageo; Manufacturer P/N: RC0402FR-074K7L; Part Number: R1030402-1%; SolidRun P/N: RE20002; Updated: 2015-02-17 20:35:06; Datasheet: <null>
RN3 = RESISTOR_DIP_4: 4 Elements 4.7kOhms 5 %; Manufacturer: CTS Electronic; Manufacturer Name: CTS Electronic; Manufacturer P/N: <null>; Power: <null>; SolidRun P/N: RN00002; Tolerance: NA; Updated: 2016-02-10 17:13:33; Datasheet: http://www.ctscorp.com/components/Datasheets/CTSChipArrayDs.pdf
SW1 = SW_DIP-5_SM: SMT 5 element DIP Switch; Manufacturer: DIPTRONICS MANUFACTURING; Manufacturer Name: DIPTRONICS MANUFACTURING; Manufacturer P/N: DMR-05(A) (P); SolidRun P/N: SW00010; Tolerance: <null>; Updated: 2016-02-10 17:13:33
SW3 = SW_SPST: Right Angle reset button 6x6x4.85mm; Manufacturer: wellbuying; Manufacturer Name: wellbuying; Manufacturer P/N: IT-1102H; SolidRun P/N: CO00570; Updated: 2016-02-10 17:13:33; Datasheet: http://www.wellbuying.com.tw/UP_pdf/IT-1102%20Series.pdf
U14 = mikroBUS: <null>; Assy: MBus; Manufacturer Name: <null>; Manufacturer P/N: <null>; PRIORITY_PN: DM00002; SolidRun P/N: DM00002; Tolerance: <null>; Updated: 2016-02-10 17:13:33; Datasheet: <null>
U15 = X76F640_SO_0: 1K-Bit I2C Serial EEPROM; Assy: DNP; Manufacturer: MicroChip; Manufacturer Name: MicroChip; SolidRun P/N: IC00312; Updated: 2016-02-10 17:13:33; Datasheet: http://ww1.microchip.com/downloads/en/DeviceDoc/20005202A.pdf
U16 = MCP3021: 10-bit ADC I2C Single Channel; Assy: MBus; Manufacturer: MicroChip; Manufacturer Name: MicroChip; Manufacturer P/N: MCP3021A4T-E/OT; SolidRun P/N: IC00710; Tolerance: <null>; Updated: 2016-02-10 17:13:33; Datasheet: http://ww1.microchip.com/downloads/en/DeviceDoc/21805B.pdf
U18 = DTSM-3: Manufacturer: BOURNS; Manufacturer Name: BOURNS; PRIORITY_PN: CO00098; SolidRun P/N: CO00098; Updated: 2016-02-10 17:13:33
U19 = PCA9555PW_1: 16-bit I2C I/O EXPANDER; Manufacturer: On Semi; Manufacturer Name: On Semi; Manufacturer P/N: PCA9655EMTTXG; SolidRun P/N: IC00921; Tolerance: <null>; Updated: 2016-02-10 17:13:33; Datasheet: http://www.onsemi.com/pub_link/Collateral/PCA9655E-D.PDF
U22 = 74LVC1G125: Single Channel Bus buffer/line driver; 3-state; Assy: DNP; Manufacturer: NXP; Manufacturer P/N: 74LVC1G125GW; SolidRun P/N: IC01056; Datasheet: http://www.nxp.com/documents/data_sheet/74LVC1G125.pdf

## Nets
GND: C71.2 C72.1 C74.2 C75.2 C77.1 C78.2 C79.2 C80.2 C81.2 C82.2 C83.2 C84.2 C85.2 C86.2 C88.2 C89.2 C94.2 C95.2 C96.2 C97.2 C98.2 C99.2 C100.2 C101.2 C103.2 C104.2 C105.2 C106.2 C107.2 C108.2 C109.2 C110.2 C111.2 C118.2 C121.2 C123.1 C124.1 C126.2 C127.2 C128.2 C129.2 C130.2 C131.2 C132.2 C133.2 C242.2 CON5.5(GND) CON6.1(VEET[0]) CON6.10(VEER[0]) CON6.11(VEER[1]) CON6.14(VEER[2]) CON6.17(VEET[1]) CON6.20(VEET[2]) J15.1 J22.1 LED3.C(CATHODE) R32.1 R39.2 R40.1 R41.1 R46.1 R49.1 R58.1 R61.1 R62.1 R72.1 R73.1 R76.1 R77.1 R79.1 R144.2 SW1.7(B4) SW1.8(B3) SW1.10(B1) SW3.1 U11.3(GND) U11.13(GND) U11.17(GND) U12.2(GND) U13.EP(VSS) U14.8(GND) U14.16(GND) U15.2(VSS) U16.2(VSS) U18.1 U19.9(VSS) U19.18(A0) U19.23(A1) U19.24(A2) U19.25(EPAD) U22.3(GND) Y1.2(GND[0]) Y1.4(GND[1]) ; also on sheet 2 3 4 5
GNDC: C116.1 C118.1 C121.1 C125.1 CON5.SH1 CON5.SH2 CON7.S1 CON7.S2 CON66.SH1 CON66.SH2 CON66.SH3 CON66.SH4 CON66.SH5 CON66.SH6 CON66.SH7 CON66.SH8 CON66.SH9 CON66.SH10 CON66.SH11 CON66.SH12 CON66.SH13 CON66.SH14 CON66.SH15 CON66.SH16 CON66.SH17 CON66.SH18 CON66.SH19 CON66.SH20 R39.1 R58.2 ; also on sheet 2 3 4 5
VCC: U22.5(VCC) ; also on sheet 2
B2B_BOOT_SEL_0: R75.2 RN3.4 ; also on sheet 2
B2B_BOOT_SEL_1: R76.2 RN3.3 ; also on sheet 2
B2B_BOOT_SEL_2: R77.2 RN3.2 ; also on sheet 2
B2B_GE0_LED1_K: CON7.B9 J22.6 ; also on sheet 2
B2B_GE0_LED2_K: CON7.B11 J22.8 ; also on sheet 2
B2B_GE_MDC: U13.7(MDC) ; also on sheet 2
B2B_GE_MDIO: U13.8(MDIO) ; also on sheet 2
B2B_I2C0_SCK: U15.1(SCL) U16.5(SCL) U19.19(SCL) ; also on sheet 2
B2B_I2C0_SDA: U15.3(SDA) U16.4(SDA) U19.20(SDA) ; also on sheet 2
B2B_MDI0_N0: T2.15 ; also on sheet 2
B2B_MDI0_N1: T2.18 ; also on sheet 2
B2B_MDI0_N2: T2.21 ; also on sheet 2
B2B_MDI0_N3: T2.24 ; also on sheet 2
B2B_MDI0_P0: T2.14 ; also on sheet 2
B2B_MDI0_P1: T2.17 ; also on sheet 2
B2B_MDI0_P2: T2.20 ; also on sheet 2
B2B_MDI0_P3: T2.23 ; also on sheet 2
B2B_MPP18: R69.2 U19.22(~{INT}) ; also on sheet 2
B2B_MPP19: U13.16(RESETn) ; also on sheet 2
B2B_MPP22: U14.10(INT) ; also on sheet 2
B2B_MPP24: U14.11(RX) ; also on sheet 2
B2B_MPP25: U14.12(TX) ; also on sheet 2
B2B_MPP26: CON6.5(SCL) U14.13(SCL) ; also on sheet 2 5
B2B_MPP27: CON6.4(SDA) U14.14(SDA) ; also on sheet 2 5
B2B_MPP29: U14.2(RST) ; also on sheet 2
B2B_MPP30: R71.2 ; also on sheet 2
B2B_MPP31: R72.2 ; also on sheet 2
B2B_MPP33: R70.2 ; also on sheet 2
B2B_MPP34: R73.2 ; also on sheet 2
B2B_MPP35: R74.2 ; also on sheet 2
B2B_MPP42: R79.2 R155.2 ; also on sheet 2
B2B_MPP43: U14.3(CS) ; also on sheet 2
B2B_MPP44: C132.1 R66.1 SW3.2 ; also on sheet 2
B2B_MPP46_REFCLK_OUT1: R48.2 ; also on sheet 2
B2B_MPP54: U14.9(PWM) ; also on sheet 2
B2B_MPP56: U14.6(MOSI) ; also on sheet 2
B2B_MPP57: R64.2 R78.2 U14.4(SCK) U22.4(Y) ; also on sheet 2
B2B_MPP58: U14.5(MISO) ; also on sheet 2
B2B_MRn: C133.1 J22.2 R68.1 U18.2 ; also on sheet 2
B2B_SRD1_Rx_N: C93.2 ; also on sheet 2
B2B_SRD1_Rx_P: C92.2 ; also on sheet 2
B2B_SRD1_Tx_N: C91.2 ; also on sheet 2
B2B_SRD1_Tx_P: C90.2 ; also on sheet 2
B2B_SRD5_Rx_N: CON6.12(RD-) ; also on sheet 2
B2B_SRD5_Rx_P: CON6.13(RD+) ; also on sheet 2
B2B_SRD5_Tx_N: CON6.19(TD-) ; also on sheet 2
B2B_SRD5_Tx_P: CON6.18(TD+) ; also on sheet 2
B2B_SYSRST_DLYn: U22.1(~{OE}) ; also on sheet 2
B2B_TPM_PP: J22.3 ; also on sheet 2
B2B_UA0_RXD: U12.4(OUT_Y2) ; also on sheet 2
B2B_UA0_TXD: U12.1(IN_A1) ; also on sheet 2
B2B_V_1V8: C94.1 C95.1 C96.1 C97.1 C98.1 R42.2 R45.1 R69.1 R75.1 SW1.6(B5) U13.11(VDDO[0]) U13.49(VDDO[1]) U13.52(VDDO[2]) ; also on sheet 2 4 5
B2B_V_3V3: C78.1 C80.1 C82.1 C85.1 C88.1 C126.1 C127.1 C131.1 CON7.A10 CON7.A12 CON7.B10 CON7.B12 FB8.1 FB9.1 FB10.1 FB11.1 J22.4 R30.2 R37.2 R38.2 R59.2 R60.2 R65.2 R66.2 R67.2 R68.2 R70.1 R71.1 R74.1 R78.1 R150.1 SW1.9(B2) U12.5(VCC) U14.7(+3.3V) U15.6(VCC) U19.21(VDD) ; also on sheet 2 3 4 5
B2B_V_MAIN: C128.1 C129.1 U14.15(+5V) ; also on sheet 2 3 4
I2C_IO_0_0: U19.1(I/O0[0]) ; also on sheet 5
I2C_IO_0_1: U19.2(I/O0[1]) ; also on sheet 5
I2C_IO_0_2: U19.3(I/O0[2])
I2C_IO_0_3: U19.4(I/O0[3]) ; also on sheet 5
I2C_IO_0_4: U19.5(I/O0[4])
I2C_IO_0_5: U19.6(I/O0[5]) ; also on sheet 4
I2C_IO_0_6: U19.7(I/O0[6]) ; also on sheet 4
I2C_IO_0_7: U19.8(I/O0[7])
I2C_IO_1_0: U19.10(I/O1[0]) ; also on sheet 5
I2C_IO_1_1: U19.11(I/O1[1]) ; also on sheet 5
I2C_IO_1_2: U19.12(I/O1[2]) ; also on sheet 5
I2C_IO_1_3: U19.13(I/O1[3]) ; also on sheet 5
I2C_IO_1_4: CON6.8(LOS) U19.14(I/O1[4])
I2C_IO_1_5: CON6.2(Tx_Fault) U19.15(I/O1[5])
I2C_IO_1_6: CON6.3(Tx_Disable) U19.16(I/O1[6])
I2C_IO_1_7: CON6.6(MODE_ABS) U19.17(I/O1[7])
Led0: R43.2 U13.14(LED[0])
LED0_K: CON7.A9 J22.7 R43.1
Led1: R44.2 U13.13(LED[1])
LED1_K: CON7.A11 J22.5 R44.1
Led2/INTn: U13.12(LED[2]/INTn)
MB_AN: U14.1(AN) U16.3(AIN)
MDI1_N0: T2.3 U13.27(MDIN[0])
MDI1_N1: T2.6 U13.23(MDIN[1])
MDI1_N2: T2.9 U13.21(MDIN[2])
MDI1_N3: T2.12 U13.17(MDIN[3])
MDI1_P0: T2.2 U13.28(MDIP[0])
MDI1_P1: T2.5 U13.24(MDIP[1])
MDI1_P2: T2.8 U13.22(MDIP[2])
MDI1_P3: T2.11 U13.18(MDIP[3])
PHY1_CFG: R45.2 U13.15(CONFIG)
Port0 Power Data+: J14.3 R54.1 T2.33
Port0 Power Data-: J14.4 R55.1 T2.36
Port0 Power Spare+: J14.2 R56.1 T2.30
Port0 Power Spare-: J14.1 R57.1 T2.27
Port1 Power Data+: J14.7 R51.1 T2.45
Port1 Power Data-: J14.8 R50.1 T2.48
Port1 Power Spare+: J14.6 R52.1 T2.42
Port1 Power Spare-: J14.5 R53.1 T2.39
RS0: CON6.7(RS0) R37.1 R40.2
RS1: CON6.9(RS1) R38.1 R41.2
SW1P2: R64.1 R144.1 R150.2 SW1.2(A2) U22.2(A)
V_3.3RX: C83.1 C84.1 CON6.15(VCCR) FB9.2
V_3.3TX: C79.1 C81.1 CON6.16(VCCT) FB8.2
V_AVDD1.8: C103.1 C104.1 C105.1 C106.1 C107.1 C108.1 C109.1 U13.3(AVDD18[0]) U13.19(AVDD18[1]) U13.26(AVDD18[2]) U13.35(AVDDC18) U13.38(AVDD18[3]) U13.39(AVDD18_OUT)
V_DCJACK_IN_FLTR: C74.1 FB6.2 ; also on sheet 3
V_P1.0: C99.1 C100.1 C242.1 U13.6(DVDD[0]) U13.40(DVDD_OUT) U13.42(DVDD[1])
V_PHY1_AVDD: C86.1 C101.1 FB10.2 U13.20(AVDD33[0]) U13.25(AVDD33[1])
V_PHY1_REG_IN: C89.1 FB11.2 U13.36(REG_IN)
XTAL_IN: C110.1 R48.1 R49.2 U13.34(XTAL_IN) Y1.3(X2)
XTAL_OUT: C111.1 U13.33(XTAL_OUT) Y1.1(X1)
N24479: R46.2 U13.30(RSET)
N28656: C87.2 U13.41(REGCAP2)
N28664: C87.1 U13.37(REGCAP1)
N16411474: C77.2 U11.1(VCCIO) U11.8(3V3OUT) U11.9(RESET#)
N16411526: C71.1 C72.2 FB5.1 U11.10(VCC)
N16411546: CON5.1(VBUS) FB5.2
N16411574: CON5.3(D+) U11.6(USBDP)
N16411628: CON5.2(D-) U11.7(USBDM)
N16411996: R30.1 R32.2 U11.15(TXD) U12.3(IN_A2)
N16412020: U11.2(RXD) U12.6(OUT_Y1)
N16876124: R60.1 R62.2 U15.4(A1)
N16876157: R59.1 R61.2 U15.5(A0)
N17004972: R42.1 U13.10(VDDO_SEL)
N17109825: C130.1 R65.1 U16.1(VDD)
N17326721: RN3.7 SW1.3(A3)
N17326723: RN3.5 SW1.5(A5)
N17326725: RN3.6 SW1.4(A4)
N17438825: R155.1 SW1.1(A1)
N17440708: LED3.A(ANODE) R67.1
N17690984: C90.1 U13.1(S_INP)
N17691016: C91.1 U13.2(S_INN)
N17691042: C92.1 U13.4(S_OUTP)
N17691068: C93.1 U13.5(S_OUTN)
N17721723: C75.1 FB6.1 J15.2
N17733801: C123.2 C124.2 T2.1 T2.4 T2.7 T2.10 T2.13 T2.16 T2.19 T2.22
N17733974: CON7.A3 T2.44
N17733976: CON7.A6 T2.43
N17733980: CON7.A4 T2.41
N17733982: CON7.A7 T2.38
N17733984: CON7.A8 T2.37
N17733988: CON7.A5 T2.40
N17733994: CON7.A2 T2.46
N17733996: CON7.A1 T2.47
N17734014: CON7.B3 T2.32
N17734016: CON7.B6 T2.31
N17734020: CON7.B4 T2.29
N17734022: CON7.B7 T2.26
N17734024: CON7.B8 T2.25
N17734028: CON7.B5 T2.28
N17734034: CON7.B2 T2.34
N17734036: CON7.B1 T2.35
N17734054: C112.2 C113.2 C114.2 C115.2 C116.2
N17734108: C112.1 R50.2
N17734119: C113.1 R51.2
N17734125: C114.1 R52.2
N17734137: C115.1 R53.2
N17734159: C117.2 C119.2 C120.2 C122.2 C125.2
N17734222: C117.1 R55.2
N17734224: C119.1 R54.2
N17734239: C120.1 R56.2
N17734243: C122.1 R57.2

Not connected (* = marked no-connect by the designer): CON5 4(ID)*; J16 1; J17 1; RN3 1 8; U11 4(CTS#)* 5(CBUS2)* 11(CBUS1)* 12(CBUS0)* 14(CBUS3)* 16(RTS#)*; U13 9(CLK125)* 29(TSTPT)* 31(HSDACN)* 32(HSDACP)* 43(RX_CTRL) 44(RXD[0]) 45(RXD[1]) 46(RX_CLK) 47(RXD[2]) 48(RXD[3]) 50(TXD[0]) 51(TXD[1]) 53(TX_CLK) 54(TXD[2]) 55(TXD[3]) 56(TX_CTRL)

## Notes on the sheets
sheet 6
- FAN Power
- microUSB to UART
- Replaced/Removed
  pullups with I2C_IO
  expander's pullups.
- SFP + defines maximum current
  withdraw from V_3.3TX and V_3.3RX as
  300mA each.
- SFP TRANSCEIVER Power
- SFP TRANSCEIVER
- AC coupling Inside
- AC coupling Inside
- SFP Shield
sheet 7
- PHY Power configurations
- PHYADD configuration
- PHY1 - SGMII1 Function as GE1 Port
- 88E1512 power configurations:
  1. using internal 1v8 and 1v0 regulators.
  2. VDDO_SEL configs VDDO to operate at 2v5/3v3.
- PHY internal
  LDO power
- PHY internal
  LDO power
- To PHY
- 88E1512 PHY configuration options:
  PHY_address=1
- From Local
  3v3_IO
- VDDO_SEL set to
  1.8v mode
- 1. PHYADD=1
  2. VDDO=3.3V
- |<- RGMII pins ->|
- From Local
  3v3_IO
- To PHY
- PHY operating
  at 3.3v
- For internal
  LDO
- --->
- MDC/MDIO from 88F6820
- 3.3 to 1.8
  voltage divider
- 25MHz CLK
  From MPP46
  (Optional)
- mechanical support for PoE module card
- PoE
- PoE
sheet 8
- Internally pulled to 0x36:
  110110
- Layout(P1): Place resistors
  as close possible to B2B
  pins.
- Do not load these signals.
  Pull-up/Pull-down must be
  placed next to B2B pins
- Frequency default Assy
- PCA9555
  16-bit I2C and SMBus I/O port with interrupt
  5V tolerant I/Os
- I/O port
  When an I/O is configured as an input, FETs Q1 and Q2 are off,
  creating a high impedance input with a weak pull-up to VDD. The
  input voltage may be raised above VDD to a maximum of 5.5 V
- RESET button
- I/O Table
- I2C Add: 0x21
- IO2_0
  IO2_1
  IO2_2
  IO2_3
  IO2_4
  IO2_5
  IO2_6
  IO2_7
  IO3_0
  IO3_1
  IO3_2
  IO3_3
  IO3_4
  IO3_5
  IO3_6
  IO3_7
- AP Reset Switch (GPIO)
- RJ-45 LEDs, Board Reset and TPM_PP
